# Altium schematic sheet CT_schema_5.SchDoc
size 368 x 245 mm
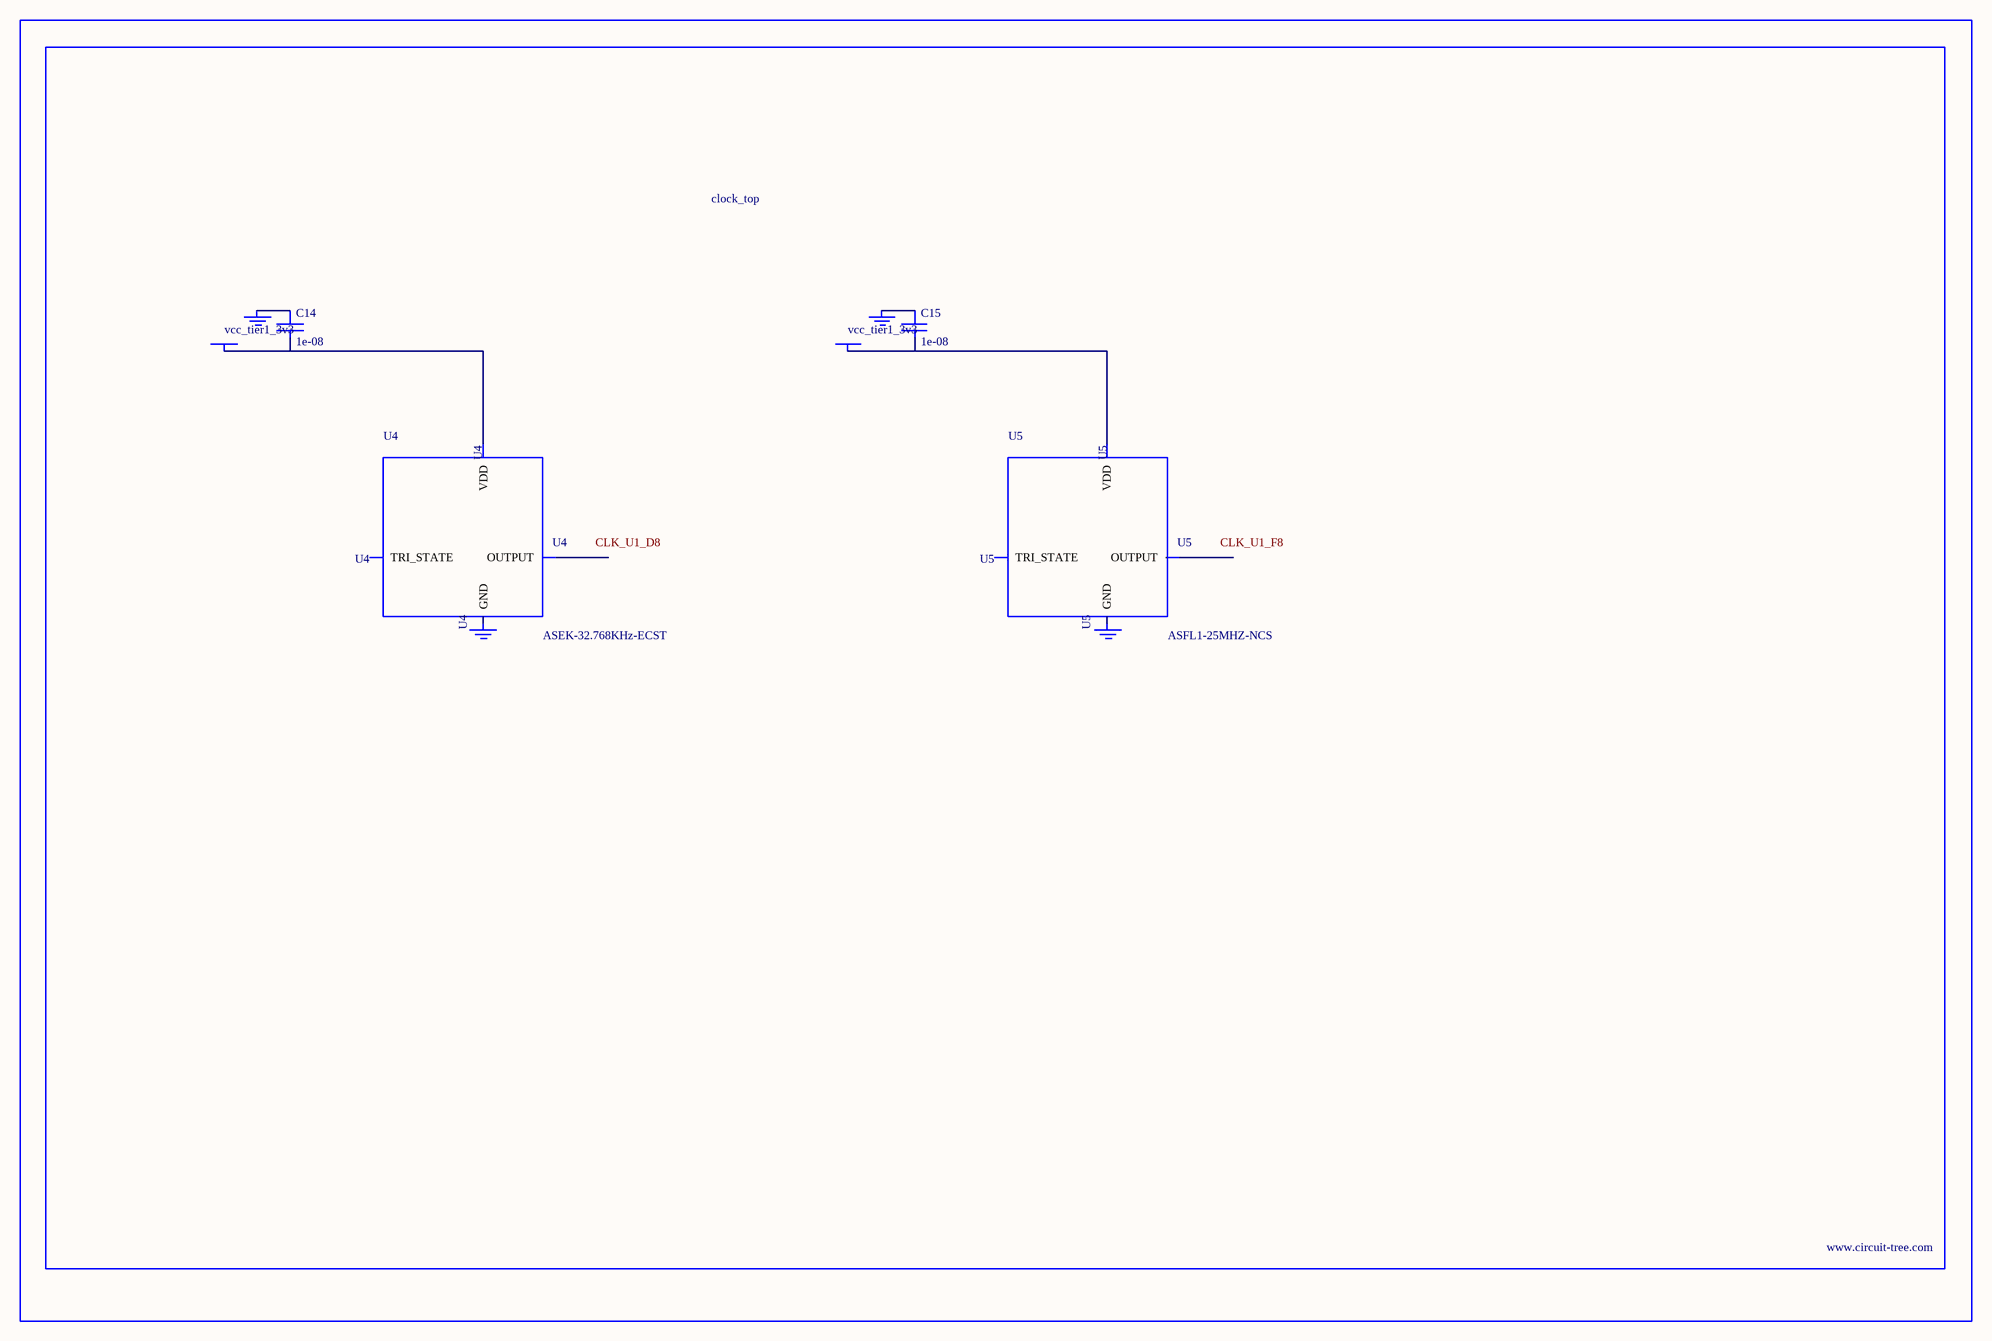
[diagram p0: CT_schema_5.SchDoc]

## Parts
BORDER4  (no value)
C14  1e-08  [C0402]
C15  1e-08  [C0402]
GND_INSTANCE_4_0  (no value)
GND_INSTANCE_4_1  (no value)
GND_INSTANCE_4_2  (no value)
GND_INSTANCE_4_3  (no value)
POWER_INSTANCE_4_0  vcc_tier1_3v3
POWER_INSTANCE_4_1  vcc_tier1_3v3
U4  ASEK-32.768KHz-ECST  [ASEK]
U5  ASFL1-25MHZ-NCS  [ASFL1]

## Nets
NetC14_1: C14.1 GND_INSTANCE_4_0.0(GND)
NetC14_2: C14.2 POWER_INSTANCE_4_0.0(PWR) U4.4(VDD)
NetC15_1: C15.1 GND_INSTANCE_4_2.0(GND)
NetC15_2: C15.2 POWER_INSTANCE_4_1.0(PWR) U5.4(VDD)

Not connected (* = marked no-connect by the designer): GND_INSTANCE_4_1 0(GND); GND_INSTANCE_4_3 0(GND); U4 1(TRI_STATE) 2(GND) 3(OUTPUT); U5 1(TRI_STATE) 2(GND) 3(OUTPUT)

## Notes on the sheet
- Labels drawn without touching a wire or pin: CLK_U1_D8, CLK_U1_F8

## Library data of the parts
BORDER4 = BORDER_PAGE4
C14 C15 = C0402C103K3RAC
GND_INSTANCE_4_0-GND_INSTANCE_4_3 = GND
POWER_INSTANCE_4_0 POWER_INSTANCE_4_1 = PWR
